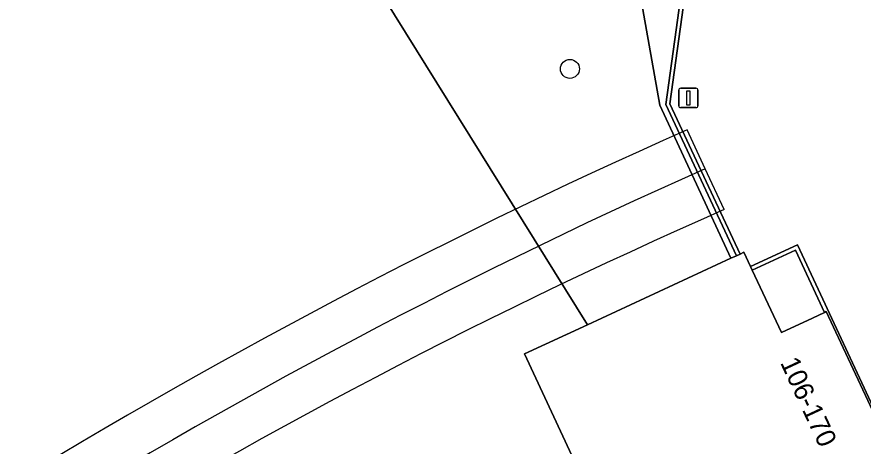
# Model space of a CAD drawing. Extents: x 155640 to 156811, y 382821 to 384049.
# Drawn here: x 156369.49 to 156413.14, y 383643.01 to 383665.14 of the extents above; entities that cross this region are included whole.
import ezdxf

# ---------------------------------------------------------------- set-up
doc = ezdxf.new("R2010")
doc.units = 0
for name, color, linetype in [('IMGEO_Boom', 7, 'Continuous'), ('IMGEO_Dek', 7, 'Continuous'), ('IMGEO_Fietspad_gesloten', 7, 'Continuous'), ('IMGEO_Groenvoorziening', 7, 'Continuous'), ('IMGEO_Lichtmast', 7, 'Continuous'), ('IMGEO_Meer_plas_ven_vijver', 7, 'Continuous'), ('IMGEO_Muur', 7, 'Continuous'), ('IMGEO_Pand', 7, 'Continuous'), ('IMGEO_Pand_nummerreeks', 7, 'Continuous'), ('IMGEO_Voetgangersgebied_gesloten', 7, 'Continuous'), ('IMGEO_Voetgangersgebied_open', 7, 'Continuous'), ('IMGEO_Voetpad_open', 7, 'Continuous')]:
    doc.layers.add(name, color=color, linetype=linetype)

msp = doc.modelspace()

# ---------------------------------------------------------------- linework, layer by layer
at = {"layer": 'IMGEO_Boom'}
msp.add_circle((156398.021, 383662.462), 0.489, dxfattribs=at)
at = {"layer": 'IMGEO_Dek'}
msp.add_lwpolyline([(156405.984, 383655.206), (156404.997, 383657.316), (156404.061, 383659.318)], dxfattribs=at)
for centre, radius, start, end in [((156524.71, 383386.919), 297.922, 113.88918, 130.50491), ((156520.895, 383392.973), 286.305, 113.66314, 130.7058)]:
    msp.add_arc(centre, radius, start, end, dxfattribs=at)
at = {"layer": 'IMGEO_Fietspad_gesloten'}
msp.add_lwpolyline([(156404.997, 383657.316), (156404.061, 383659.318)], dxfattribs=at)
for centre, radius, start, end in [((156524.71, 383386.919), 297.922, 113.88918, 130.50491), ((156526.23, 383385.16), 297.937, 114.01083, 130.50472)]:
    msp.add_arc(centre, radius, start, end, dxfattribs=at)
at = {"layer": 'IMGEO_Groenvoorziening'}
msp.add_lwpolyline([(156400.777, 383671.143), (156397.859, 383672.624), (156396.207, 383670.632), (156391.957, 383673.269), (156388.526, 383666.353), (156388.405, 383666.182), (156398.921, 383649.266), (156406.329, 383652.699), (156402.667, 383660.593)], close=True, dxfattribs=at)
at = {"layer": 'IMGEO_Lichtmast'}
for p, q in [((156403.634, 383660.565), (156403.634, 383661.365)), ((156403.634, 383661.365), (156403.634, 383660.565)), ((156403.734, 383661.465), (156404.524, 383661.465)), ((156404.524, 383661.465), (156403.734, 383661.465)), ((156404.624, 383661.365), (156404.624, 383660.565)), ((156404.624, 383660.565), (156404.624, 383661.365)), ((156404.524, 383660.465), (156403.734, 383660.465)), ((156403.734, 383660.465), (156404.524, 383660.465))]:
    msp.add_line(p, q, dxfattribs=at)
msp.add_lwpolyline([(156404.054, 383661.34), (156404.204, 383661.34), (156404.204, 383660.59), (156404.054, 383660.59), (156404.054, 383661.34)], dxfattribs=at)
for centre, start, end in [((156403.734, 383661.365), 90, 180), ((156403.734, 383661.365), 90, 180), ((156404.524, 383661.365), 0, 90), ((156404.524, 383661.365), 360, 90), ((156403.734, 383660.565), 180, 270), ((156403.734, 383660.565), 180, 270), ((156404.524, 383660.565), 270, 0), ((156404.524, 383660.565), 270, 0)]:
    msp.add_arc(centre, 0.1, start, end, dxfattribs=at)
at = {"layer": 'IMGEO_Meer_plas_ven_vijver'}
msp.add_lwpolyline([(156409.738, 383617.568), (156395.678, 383647.763), (156398.921, 383649.266), (156388.405, 383666.182), (156388.164, 383666.029), (156381.02, 383677.599), (156384.468, 383688.597), (156384.494, 383688.593), (156385.008, 383692.092), (156370.759, 383694.081), (156370.875, 383694.938), (156371.987, 383694.787), (156372.993, 383701.906), (156370.31, 383702.303), (156370.445, 383703.217), (156371.61, 383703.045), (156372.608, 383710.192), (156371.421, 383710.367), (156371.545, 383711.205), (156417.388, 383704.778)], dxfattribs=at)
at = {"layer": 'IMGEO_Muur'}
msp.add_lwpolyline([(156409.602, 383685.242), (156409.281, 383685.287), (156406.898, 383679.708), (156406.259, 383675.274), (156405.007, 383675.431), (156402.962, 383660.62), (156406.607, 383652.828), (156406.798, 383652.916), (156403.183, 383660.665), (156405.194, 383675.202), (156406.522, 383675.039), (156407.185, 383679.634)], close=True, dxfattribs=at)
msp.add_lwpolyline([(156425.737, 383619.126), (156409.758, 383653.398), (156407.34, 383652.267), (156407.426, 383652.083), (156409.651, 383653.114), (156411.15, 383649.901), (156411.248, 383649.947), (156415.163, 383641.581)], dxfattribs=at)
at = {"layer": 'IMGEO_Pand'}
msp.add_lwpolyline([(156414.442, 383641.243), (156415.055, 383641.53), (156415.163, 383641.581), (156411.248, 383649.947), (156411.15, 383649.901), (156410.541, 383649.616), (156408.931, 383648.863), (156407.426, 383652.083), (156407.34, 383652.267), (156406.994, 383653.007), (156406.798, 383652.916), (156406.607, 383652.828), (156406.329, 383652.699), (156398.921, 383649.266), (156395.678, 383647.763), (156409.738, 383617.568), (156417.016, 383620.957), (156419.863, 383622.283), (156420.487, 383622.573), (156421.652, 383623.116), (156422.668, 383623.589)], close=True, dxfattribs=at)
at = {"layer": 'IMGEO_Voetgangersgebied_gesloten'}
msp.add_lwpolyline([(156405.984, 383655.206), (156404.997, 383657.316)], dxfattribs=at)
msp.add_lwpolyline([(156409.651, 383653.114), (156407.426, 383652.083), (156408.931, 383648.863), (156410.541, 383649.616), (156411.15, 383649.901)], close=True, dxfattribs=at)
for centre, radius, start, end in [((156526.23, 383385.16), 297.937, 114.01083, 130.50472), ((156520.895, 383392.973), 286.305, 113.66314, 130.7058)]:
    msp.add_arc(centre, radius, start, end, dxfattribs=at)
at = {"layer": 'IMGEO_Voetgangersgebied_open'}
msp.add_lwpolyline([(156414.878, 383684.502), (156409.602, 383685.242), (156407.185, 383679.634), (156406.522, 383675.039), (156405.194, 383675.202), (156403.183, 383660.665), (156406.798, 383652.916), (156406.994, 383653.007), (156407.34, 383652.267), (156409.758, 383653.398), (156425.737, 383619.126)], dxfattribs=at)
at = {"layer": 'IMGEO_Voetpad_open'}
msp.add_lwpolyline([(156405.007, 383675.431), (156405.277, 383677.405), (156405.034, 383677.437), (156404.977, 383677.465), (156403.554, 383677.003), (156400.777, 383671.143), (156402.667, 383660.593), (156406.329, 383652.699), (156406.607, 383652.828), (156402.962, 383660.62)], close=True, dxfattribs=at)

# ---------------------------------------------------------------- texts
at = {"layer": 'IMGEO_Pand_nummerreeks'}
msp.add_text('106-170', height=1, rotation=294.9807, dxfattribs=at).set_placement((156408.852, 383647.319))

doc.saveas('drawing.dxf')
